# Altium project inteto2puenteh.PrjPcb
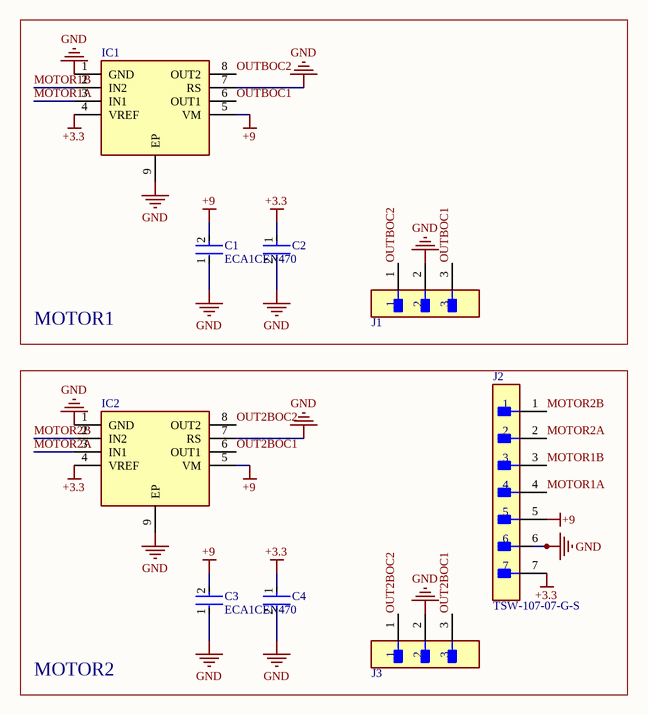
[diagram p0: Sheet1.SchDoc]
1 sheet, 9 parts. Net scope: global (net labels, ports and power ports of the same name join across sheets).
Board file: PCB1.PcbDoc

## Sheet Sheet1.SchDoc
size A4; SheetNumber: 1; SheetTotal: 1

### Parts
C1  ECA1CEN470  [FP-RAD-TH-D_6_3_0_5-L_11-MFG]
C2  C1206C153K5RAC  [FP-C1206C-EB-MFG]  (value not drawn)
C3  ECA1CEN470  [FP-RAD-TH-D_6_3_0_5-L_11-MFG]
C4  C1206C153K5RAC  [FP-C1206C-EB-MFG]  (value not drawn)
IC1  TB67H451FNG  [SOIC127P600X170-9N]  (value not drawn)
IC2  TB67H451FNG  [SOIC127P600X170-9N]  (value not drawn)
J1  TSW-103-14-G-S  [FP-TSW-103-14-G-S-MFG]  (value not drawn)
J2  TSW-107-07-G-S  [FP-TSW-107-07-G-S-MFG]
J3  TSW-103-14-G-S  [FP-TSW-103-14-G-S-MFG]  (value not drawn)

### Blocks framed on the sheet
MOTOR1: C1 C2 IC1 J1
MOTOR2: C3 C4 IC2 J2 J3

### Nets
+3.3: C2.1 C4.1 IC1.4(VREF) IC2.4(VREF) J2.7
+9: C1.2 C3.2 IC1.5(VM) IC2.5(VM) J2.5
GND: C1.1 C2.2 C3.1 C4.2 IC1.1(GND) IC1.7(RS) IC1.9(EP) IC2.1(GND) IC2.7(RS) IC2.9(EP) J1.2 J2.6 J3.2
MOTOR1A: IC1.3(IN1) J2.4
MOTOR1B: IC1.2(IN2) J2.3
MOTOR2A: IC2.3(IN1) J2.2
MOTOR2B: IC2.2(IN2) J2.1
OUT2BOC1: IC2.6(OUT1) J3.3
OUT2BOC2: IC2.8(OUT2) J3.1
OUTBOC1: IC1.6(OUT1) J1.3
OUTBOC2: IC1.8(OUT2) J1.1

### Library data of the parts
C1 C3 = CMP-05427-001931-1: Aluminum Electrolytic Capacitors (Radial Lead Type) 47uF ±20% 16V; Ripple Current: 100mA; Lead/Base Style: Straight
C2 C4 = CMP-03020-027494-1: C1206 15,000 pF X7R 10.00% 50 V; Manufacturer: KEMET; Tolerance: 0.1; Voltage Rating: 50 V; Material: Ceramic; Temperature Coefficient: 15%; Automotive Grade: Grade 0
IC1 IC2 = TB67H451FNG: Integrated Circuit; Manufacturer_Name: Toshiba
J1 J3 = CMP-02766-001743-1: CONN HEADER VERT 3POS 2.54MM; Max Voltage Rating (AC): 550V; Number of Positions: 3; Max Current Rating: 7.6A; Gender: Male
J2 = CMP-02766-000065-1: CONN HEADER VERT 7POS 2.54MM; Manufacturer: SAMTEC; Conn Orientation: Straight; Number Of Contacts: 7; Conn Gender: Male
